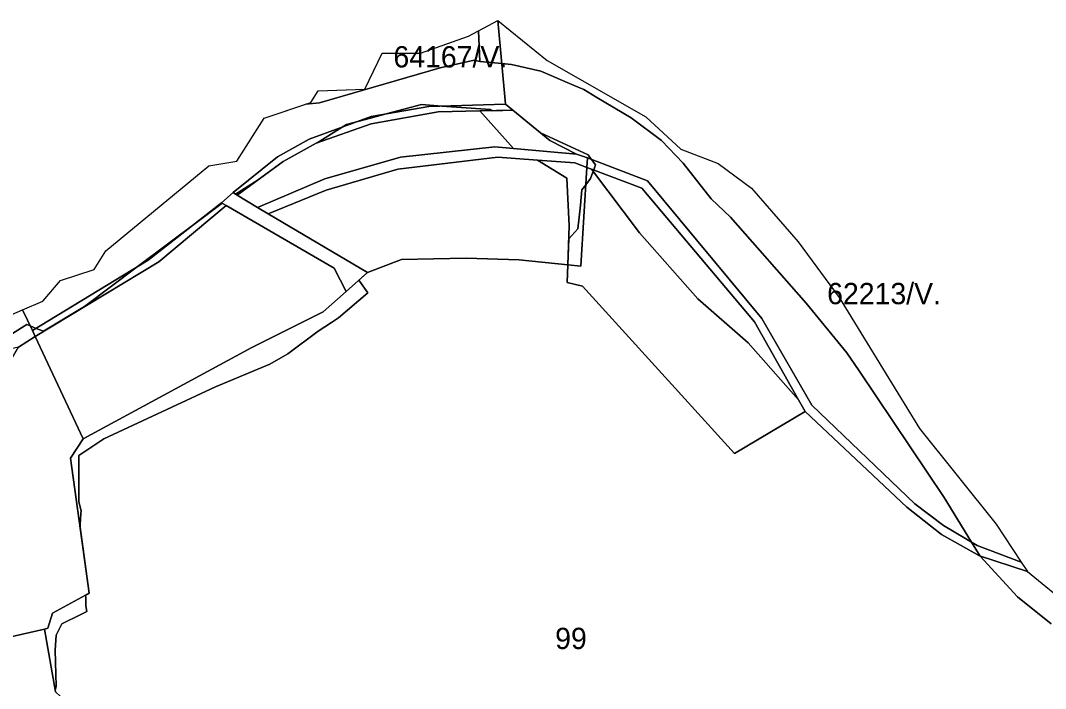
# Model space of a CAD drawing. Extents: x -502026 to -497664, y -1143484 to -1138019.
# Drawn here: x -498405.5 to -498019.9, y -1138760.2 to -1138509 of the extents above; entities that cross this region are included whole.
import ezdxf

# ---------------------------------------------------------------- set-up
doc = ezdxf.new("R2010")
doc.units = 0
for name, color, linetype in [('37', 7, 'Continuous'), ('43', 7, 'Continuous'), ('55', 7, 'Continuous'), ('62', 7, 'Continuous'), ('7', 7, 'Continuous')]:
    doc.layers.add(name, color=color, linetype=linetype)

msp = doc.modelspace()

# ---------------------------------------------------------------- linework, layer by layer
at = {"layer": '37'}
for points in [[(-498220.01, -1138557.11), (-498227.15, -1138556.47), (-498262.61, -1138560.37), (-498291.08, -1138568.6), (-498316.38, -1138579.27), (-498324.07, -1138574.72), (-498306.77, -1138562), (-498294.35, -1138555.16), (-498273.58, -1138547.88), (-498248.46, -1138543.31), (-498232.76, -1138543.04)], [(-498196.39, -1138559.22), (-498220.01, -1138557.11), (-498232.76, -1138543.04), (-498220.28, -1138542.78), (-498206.38, -1138554.13)], [(-498210.99, -1138561.52), (-498200, -1138568.28), (-498199.13, -1138586.18), (-498199.63, -1138600.87), (-498217.93, -1138598.98), (-498237.93, -1138598.43), (-498262.25, -1138598.9), (-498275.01, -1138603.76), (-498312.34, -1138581.66), (-498290.59, -1138572.82), (-498263.52, -1138564.86), (-498226, -1138560.41)], [(-498324.07, -1138574.72), (-498316.38, -1138579.27), (-498312.34, -1138581.66), (-498275.01, -1138603.76), (-498283.02, -1138610.93), (-498287.49, -1138602.09), (-498328.2, -1138578.52), (-498329.95, -1138577.51), (-498325.49, -1138573.69)], [(-498283.02, -1138610.93), (-498291.63, -1138618.55), (-498318.46, -1138631.99), (-498381.9, -1138666.35), (-498400.04, -1138627.79), (-498353.52, -1138599.7), (-498328.2, -1138578.52), (-498287.49, -1138602.09)], [(-498381.9, -1138666.35), (-498386.67, -1138673.51), (-498379.67, -1138724.33), (-498393.46, -1138731.8), (-498395.29, -1138737.53), (-498396.46, -1138737.8), (-498470.02, -1138754.55), (-498494.11, -1138757.49), (-498496.57, -1138742.3), (-498500.07, -1138720.75), (-498502.55, -1138694.61), (-498504.85, -1138670.32), (-498486.68, -1138665.96), (-498484.3, -1138671.25), (-498476.7, -1138666.92), (-498450.91, -1138657.54), (-498425.15, -1138648.21), (-498415.68, -1138643.27), (-498410.6, -1138639.29), (-498406.31, -1138631.8), (-498400.04, -1138627.79)]]:
    msp.add_lwpolyline(points, close=True, dxfattribs=at)
at = {"layer": '43'}
for points in [[(-498223.08, -1138540.49), (-498251.96, -1138541.32), (-498273.66, -1138545.14), (-498296.95, -1138553.65), (-498308.8, -1138560.33), (-498325.49, -1138573.69), (-498329.95, -1138577.51), (-498357.49, -1138599.14), (-498401.06, -1138625.62), (-498404.73, -1138617.81), (-498397.13, -1138614.5), (-498390.46, -1138606.73), (-498377.77, -1138602.58), (-498373.37, -1138595.61), (-498334.72, -1138563.66), (-498324.08, -1138561.94), (-498313.89, -1138545.78), (-498296.3, -1138539.9), (-498293.5, -1138535.42), (-498275.95, -1138534.78), (-498269.43, -1138521.3), (-498255.04, -1138521.3), (-498237.05, -1138514.94), (-498233.47, -1138513.02), (-498226.02, -1138509.02)], [(-498029.08, -1138712.62), (-498045.66, -1138706.43), (-498058.26, -1138698.88), (-498069.07, -1138690.69), (-498107.79, -1138653.62), (-498126.63, -1138621.01), (-498169.72, -1138569.32), (-498192.26, -1138560.6), (-498196.39, -1138559.22), (-498206.38, -1138554.13), (-498220.28, -1138542.78), (-498223.08, -1138540.49), (-498226.02, -1138509.02), (-498207.43, -1138524.08), (-498170.33, -1138545.2), (-498157.13, -1138557.36), (-498143.06, -1138562.8), (-498130.59, -1138572.08), (-498113, -1138592.23), (-498097.53, -1138613.2), (-498067.35, -1138662.4), (-498038.56, -1138698.4)], [(-498190.75, -1138564.88), (-498172.66, -1138588.88), (-498150.72, -1138613.7), (-498131.79, -1138630.24), (-498112.84, -1138651.63), (-498110.37, -1138656.01), (-498136.88, -1138671.76), (-498194.12, -1138608.93), (-498199.85, -1138607.49), (-498199.63, -1138600.87), (-498194.8, -1138601.37), (-498192.49, -1138564.23)], [(-498112.84, -1138651.63), (-498131.79, -1138630.24), (-498150.72, -1138613.7), (-498172.66, -1138588.88), (-498190.75, -1138564.88), (-498171.74, -1138572.02), (-498129.41, -1138622.29)]]:
    msp.add_lwpolyline(points, close=True, dxfattribs=at)
msp.add_lwpolyline([(-498392.35, -1138761.47), (-498396.46, -1138737.8), (-498395.29, -1138737.53), (-498393.46, -1138731.8), (-498379.67, -1138724.33), (-498386.67, -1138673.51), (-498381.9, -1138666.35), (-498318.46, -1138631.99), (-498291.63, -1138618.55), (-498283.02, -1138610.93), (-498275.01, -1138603.76), (-498262.25, -1138598.9), (-498237.93, -1138598.43), (-498217.93, -1138598.98), (-498199.63, -1138600.87), (-498199.85, -1138607.49), (-498194.12, -1138608.93), (-498136.88, -1138671.76), (-498110.37, -1138656.01), (-498072.09, -1138691.96), (-498059.09, -1138702.3), (-498044.82, -1138710.25), (-498026.73, -1138716.15), (-498008.21, -1138731.31)], dxfattribs=at)
at = {"layer": '55'}
for points in [[(-498220.28, -1138542.78), (-498232.76, -1138543.04), (-498248.46, -1138543.31), (-498273.58, -1138547.88), (-498294.35, -1138555.16), (-498306.77, -1138562), (-498324.07, -1138574.72), (-498325.49, -1138573.69), (-498308.8, -1138560.33), (-498296.95, -1138553.65), (-498273.66, -1138545.14), (-498251.96, -1138541.32), (-498223.08, -1138540.49)], [(-498220.01, -1138557.11), (-498196.39, -1138559.22), (-498192.26, -1138560.6), (-498192.49, -1138564.23), (-498196.94, -1138562.56), (-498210.99, -1138561.52), (-498226, -1138560.41), (-498263.52, -1138564.86), (-498290.59, -1138572.82), (-498312.34, -1138581.66), (-498316.38, -1138579.27), (-498291.08, -1138568.6), (-498262.61, -1138560.37), (-498227.15, -1138556.47)], [(-498192.49, -1138564.23), (-498194.8, -1138601.37), (-498199.63, -1138600.87), (-498199.13, -1138586.18), (-498200, -1138568.28), (-498210.99, -1138561.52), (-498196.94, -1138562.56)], [(-498029.08, -1138712.62), (-498026.73, -1138716.15), (-498044.82, -1138710.25), (-498059.09, -1138702.3), (-498072.09, -1138691.96), (-498110.37, -1138656.01), (-498112.84, -1138651.63), (-498129.41, -1138622.29), (-498171.74, -1138572.02), (-498190.75, -1138564.88), (-498192.49, -1138564.23), (-498192.26, -1138560.6), (-498169.72, -1138569.32), (-498126.63, -1138621.01), (-498107.79, -1138653.62), (-498069.07, -1138690.69), (-498058.26, -1138698.88), (-498045.66, -1138706.43)], [(-498328.2, -1138578.52), (-498353.52, -1138599.7), (-498400.04, -1138627.79), (-498401.06, -1138625.62), (-498357.49, -1138599.14), (-498329.95, -1138577.51)], [(-498401.06, -1138625.62), (-498400.04, -1138627.79), (-498406.31, -1138631.8), (-498456.05, -1138643.09), (-498471.08, -1138648.09), (-498480.29, -1138655.94), (-498486.68, -1138665.96), (-498504.85, -1138670.32), (-498505.4, -1138664.49), (-498488.04, -1138660.51), (-498482.03, -1138651.11), (-498473.31, -1138642.77), (-498453.95, -1138637.92), (-498440.91, -1138630.98), (-498439.4, -1138630.74), (-498436.28, -1138630.24), (-498431.47, -1138629.47), (-498404.73, -1138617.81)]]:
    msp.add_lwpolyline(points, close=True, dxfattribs=at)
at = {"layer": '62'}
for points in [[(-498017.75, -1138735.87), (-498030.5, -1138725.75), (-498044.54, -1138710.35), (-498047.74, -1138705.18), (-498058.12, -1138688.37), (-498090, -1138640.75), (-498094.66, -1138634), (-498109.97, -1138615.25), (-498138.41, -1138583), (-498145.66, -1138576.12), (-498156.25, -1138562.62), (-498164.34, -1138554.12), (-498175.81, -1138545.62), (-498188.7, -1138537.95), (-498193.66, -1138535), (-498197.3, -1138533.45), (-498209.81, -1138528.12), (-498220.84, -1138525.62), (-498224.5, -1138525.24), (-498232.75, -1138524.37), (-498233.18, -1138512.86), (-498226.02, -1138509.02), (-498207.43, -1138524.08), (-498170.33, -1138545.2), (-498157.13, -1138557.36), (-498143.06, -1138562.8), (-498130.59, -1138572.08), (-498113, -1138592.23), (-498097.53, -1138613.2), (-498067.35, -1138662.4), (-498038.56, -1138698.4), (-498029.08, -1138712.62), (-498026.73, -1138716.15), (-498008.21, -1138731.31)], [(-498431.47, -1138629.47), (-498404.73, -1138617.81), (-498397.13, -1138614.5), (-498390.46, -1138606.73), (-498377.77, -1138602.58), (-498373.37, -1138595.61), (-498334.72, -1138563.66), (-498324.08, -1138561.94), (-498313.89, -1138545.78), (-498298.19, -1138540.53), (-498298.17, -1138540.53), (-498293.06, -1138540), (-498247.62, -1138526.87), (-498234.87, -1138523.87), (-498232.75, -1138524.37), (-498224.5, -1138525.24), (-498220.84, -1138525.62), (-498209.81, -1138528.12), (-498197.3, -1138533.45), (-498193.66, -1138535), (-498188.7, -1138537.95), (-498175.81, -1138545.62), (-498164.34, -1138554.12), (-498156.25, -1138562.62), (-498145.66, -1138576.12), (-498138.41, -1138583), (-498109.97, -1138615.25), (-498094.66, -1138634), (-498090, -1138640.75), (-498058.12, -1138688.37), (-498047.74, -1138705.18), (-498044.54, -1138710.35), (-498030.5, -1138725.75), (-498017.75, -1138735.87)], [(-498422.82, -1138635.55), (-498403.09, -1138623.37), (-498401.89, -1138623.86), (-498399.64, -1138624.76), (-498396.87, -1138625.87), (-498381.41, -1138616.54), (-498361.62, -1138601.65), (-498339.37, -1138584.91), (-498329.72, -1138577.64), (-498329.95, -1138577.51), (-498325.49, -1138573.69), (-498324.68, -1138574.28), (-498316.5, -1138569.15), (-498306.77, -1138562), (-498294.35, -1138555.16), (-498293.97, -1138555.03), (-498284.54, -1138549.12), (-498282.89, -1138548.08), (-498278.63, -1138546.96), (-498273.88, -1138545.7), (-498267.95, -1138544.13), (-498254.65, -1138540.62), (-498247.02, -1138541.18), (-498228.76, -1138542.51), (-498227.84, -1138542.94), (-498220.28, -1138542.78), (-498209.94, -1138551.22), (-498192.04, -1138559.51), (-498190.81, -1138561.16), (-498190.28, -1138561.87), (-498189.21, -1138563.29), (-498189.91, -1138565.2), (-498189.97, -1138565.36), (-498190.1, -1138565.74), (-498190.59, -1138567.09), (-498191.1, -1138568.48), (-498192.9, -1138570.81), (-498194.39, -1138572.74), (-498194.86, -1138578.4), (-498195.34, -1138582.95), (-498195.81, -1138587.38), (-498199.3, -1138591.11), (-498199.63, -1138600.87), (-498217.93, -1138598.98), (-498237.93, -1138598.43), (-498262.25, -1138598.9), (-498275.01, -1138603.76), (-498278.25, -1138606.66), (-498274.81, -1138611.37), (-498285.84, -1138620.75), (-498288.51, -1138622.54), (-498293.5, -1138625.87), (-498304.97, -1138634.37), (-498311.75, -1138638.25), (-498332.16, -1138646.75), (-498374.22, -1138666.25), (-498383.56, -1138672.62), (-498383.56, -1138690), (-498382.72, -1138693.37), (-498382.81, -1138694.49), (-498383.12, -1138698.5), (-498383.09, -1138699.49), (-498379.67, -1138724.33), (-498381.16, -1138725.14), (-498381, -1138725.75), (-498381, -1138729.12), (-498380.59, -1138731.25), (-498382.78, -1138732.33), (-498389.94, -1138735.87), (-498392.06, -1138740.12), (-498392.5, -1138745.75), (-498392.06, -1138759.25), (-498392.44, -1138760.97)], [(-498392.44, -1138760.97), (-498392.06, -1138759.25), (-498392.5, -1138745.75), (-498392.06, -1138740.12), (-498389.94, -1138735.87), (-498382.78, -1138732.33), (-498380.59, -1138731.25), (-498381, -1138729.12), (-498381, -1138725.75), (-498381.16, -1138725.14), (-498379.67, -1138724.33), (-498383.09, -1138699.49), (-498383.12, -1138698.5), (-498382.81, -1138694.49), (-498382.72, -1138693.37), (-498383.56, -1138690), (-498383.56, -1138672.62), (-498374.22, -1138666.25), (-498332.16, -1138646.75), (-498311.75, -1138638.25), (-498304.97, -1138634.37), (-498293.5, -1138625.87), (-498288.51, -1138622.54), (-498285.84, -1138620.75), (-498274.81, -1138611.37), (-498278.25, -1138606.66), (-498275.01, -1138603.76), (-498262.25, -1138598.9), (-498237.93, -1138598.43), (-498217.93, -1138598.98), (-498199.63, -1138600.87), (-498199.3, -1138591.11), (-498195.81, -1138587.38), (-498195.34, -1138582.95), (-498194.86, -1138578.4), (-498194.39, -1138572.74), (-498192.9, -1138570.81), (-498191.1, -1138568.48), (-498190.59, -1138567.09), (-498190.1, -1138565.74), (-498189.97, -1138565.36), (-498189.91, -1138565.2), (-498189.21, -1138563.29), (-498190.28, -1138561.87), (-498190.81, -1138561.16), (-498192.04, -1138559.51), (-498209.94, -1138551.22), (-498220.28, -1138542.78), (-498227.84, -1138542.94), (-498228.76, -1138542.51), (-498247.02, -1138541.18), (-498254.65, -1138540.62), (-498267.95, -1138544.13), (-498273.88, -1138545.7), (-498278.63, -1138546.96), (-498282.89, -1138548.08), (-498284.54, -1138549.12), (-498293.97, -1138555.03), (-498294.35, -1138555.16), (-498306.77, -1138562), (-498316.5, -1138569.15), (-498324.68, -1138574.28), (-498325.49, -1138573.69), (-498329.95, -1138577.51), (-498329.72, -1138577.64), (-498339.37, -1138584.91), (-498361.62, -1138601.65), (-498381.41, -1138616.54), (-498396.87, -1138625.87), (-498399.64, -1138624.76), (-498401.89, -1138623.86), (-498403.09, -1138623.37), (-498422.82, -1138635.55)]]:
    msp.add_lwpolyline(points, dxfattribs=at)
msp.add_lwpolyline([(-498232.75, -1138524.37), (-498234.87, -1138523.87), (-498247.62, -1138526.87), (-498293.06, -1138540), (-498298.17, -1138540.53), (-498296.3, -1138539.9), (-498293.5, -1138535.42), (-498275.95, -1138534.78), (-498269.43, -1138521.3), (-498255.04, -1138521.3), (-498237.05, -1138514.94), (-498233.47, -1138513.02), (-498233.18, -1138512.86)], close=True, dxfattribs=at)
at = {"layer": '7'}
msp.add_lwpolyline([(-498371.63, -1138874.41), (-498396.55, -1138872.26), (-498418.98, -1138868.62), (-498446.37, -1138838.19), (-498477, -1138818.54), (-498503.51, -1138801.96), (-498535.67, -1138787.24), (-498490.02, -1138774.59), (-498494.11, -1138757.49), (-498470.02, -1138754.55), (-498396.46, -1138737.8), (-498392.35, -1138761.47), (-498358.52, -1138793.04), (-498319.89, -1138837.58), (-498347.43, -1138860.73)], close=True, dxfattribs=at)

# ---------------------------------------------------------------- texts
at = {"layer": '62'}
for s, p in [('64167/V.', (-498265.24, -1138526.66)), ('62213/V.', (-498102.08, -1138615.68)), ('99', (-498204.39, -1138745.33))]:
    msp.add_text(s, height=8, dxfattribs=at).set_placement(p)

doc.saveas('drawing.dxf')
